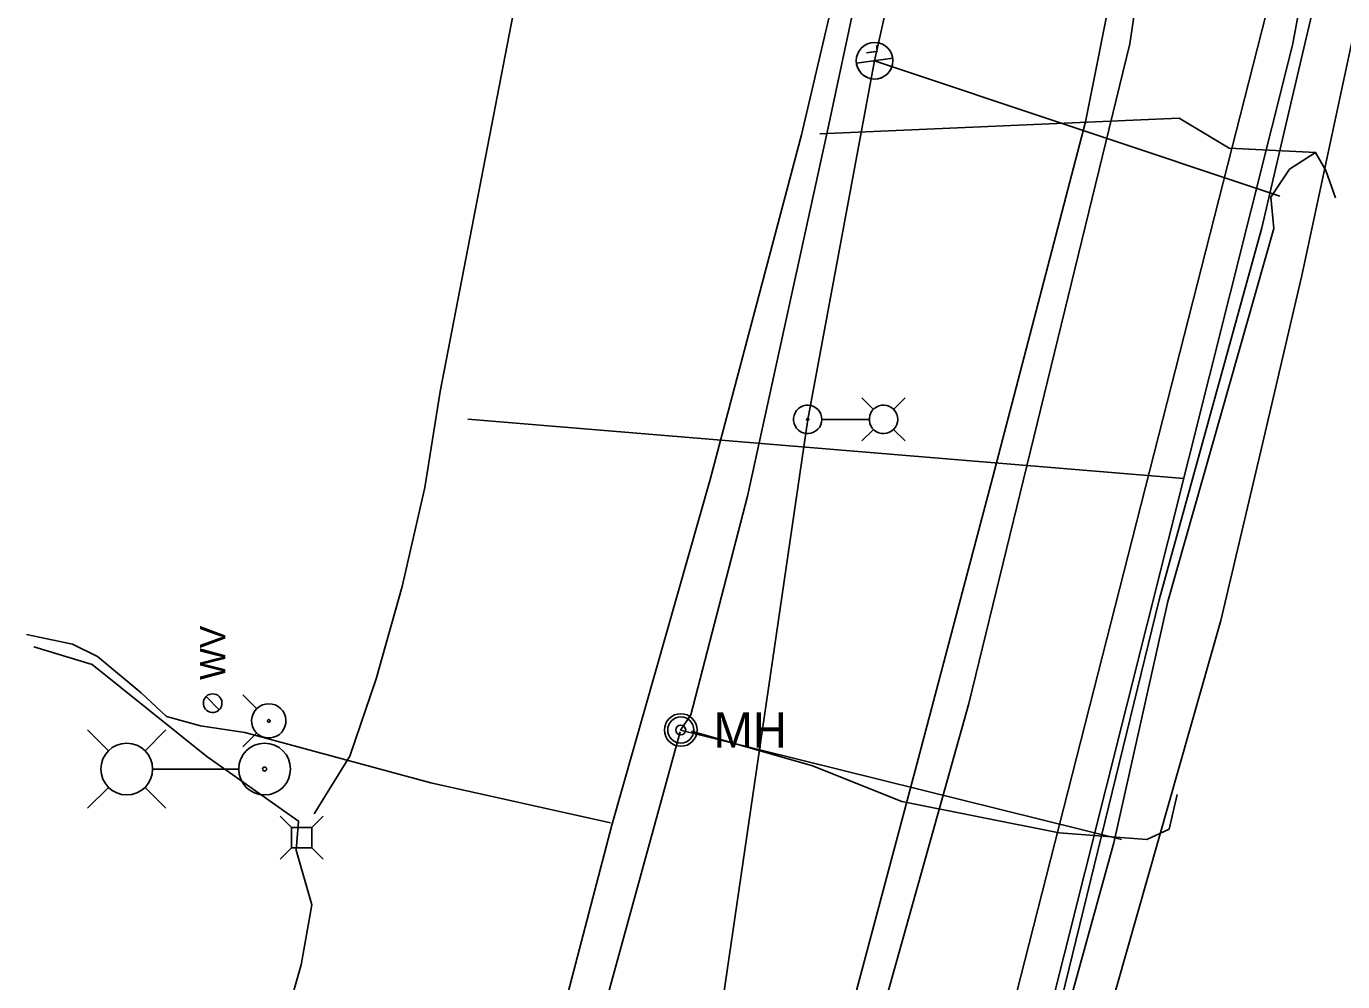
# Model space of a CAD drawing. Extents: x 596028 to 606371, y 330010 to 403088.
# Drawn here: x 604917.4 to 605119, y 336464.1 to 336610.4 of the extents above; entities that cross this region are included whole.
import ezdxf

# ---------------------------------------------------------------- set-up
doc = ezdxf.new("R2010")
doc.units = 0
for name, color, linetype in [('Default', 7, 'Continuous'), ('E_LTG', 7, 'Continuous'), ('E_LTG_CID', 7, 'Continuous'), ('E_UTL_E', 7, 'Continuous'), ('E_UTL_E_UG', 7, 'Continuous'), ('E_UTL_G_UG', 7, 'Continuous'), ('E_UTL_SAN_UG', 7, 'Continuous'), ('E_UTL_TV_UG', 7, 'Continuous'), ('E_UTL_W', 7, 'Continuous'), ('E_UTL_W_UG', 7, 'Continuous'), ('E_UTL_WHydrant', 7, 'Continuous')]:
    doc.layers.add(name, color=color, linetype=linetype)

# ---------------------------------------------------------------- blocks, each defined once
blk = doc.blocks.new('MH')
at = {"layer": 'Default'}
for radius in [15.2, 12.2, 4.57]:
    blk.add_circle((0, 0), radius, dxfattribs=at)
blk.add_text('MH', height=32.92, dxfattribs=at).set_placement((30.5, -16.5))
blk = doc.blocks.new('_U272')
at = {"layer": 'E_LTG'}
blk.add_lwpolyline([(0.001, -0.171), (0.001, 0.172)], dxfattribs=at)
blk.add_circle((0.001, 0), 0.171, dxfattribs=at)
blk.add_arc((0.001, 0), 0.171, 90, 270, dxfattribs=at)
blk.add_text('L', height=0.108, dxfattribs=at).set_placement((0.066, -0.042))

msp = doc.modelspace()

# ---------------------------------------------------------------- linework, layer by layer
at = {"layer": 'E_LTG'}
for points in [[(605039.28, 336550.19), (605039.24, 336550.61), (605039.13, 336551), (605038.94, 336551.37), (605038.68, 336551.7), (605038.37, 336551.97), (605038.01, 336552.17), (605037.62, 336552.31), (605037.21, 336552.37), (605036.8, 336552.35), (605036.4, 336552.25), (605036.02, 336552.08), (605035.68, 336551.84), (605035.4, 336551.54), (605035.17, 336551.19), (605035.02, 336550.81), (605034.94, 336550.4), (605034.94, 336549.99), (605035.02, 336549.58), (605035.17, 336549.2), (605035.4, 336548.85), (605035.68, 336548.55), (605036.02, 336548.31), (605036.4, 336548.14), (605036.8, 336548.04), (605037.21, 336548.02), (605037.62, 336548.08), (605038.01, 336548.22), (605038.37, 336548.42), (605038.68, 336548.69), (605038.94, 336549.02), (605039.13, 336549.39), (605039.24, 336549.78), (605039.28, 336550.19)], [(605047.19, 336551.72), (605045.41, 336553.49)], [(605050.89, 336550.19), (605050.85, 336550.61), (605050.73, 336551), (605050.54, 336551.37), (605050.29, 336551.7), (605049.97, 336551.97), (605049.62, 336552.17), (605049.22, 336552.31), (605048.82, 336552.37), (605048.4, 336552.35), (605048, 336552.25), (605047.62, 336552.08), (605047.29, 336551.84), (605047, 336551.54), (605046.78, 336551.19), (605046.62, 336550.81), (605046.55, 336550.4), (605046.55, 336549.99), (605046.62, 336549.58), (605046.78, 336549.2), (605047, 336548.85), (605047.29, 336548.55), (605047.62, 336548.31), (605048, 336548.14), (605048.4, 336548.04), (605048.82, 336548.02), (605049.22, 336548.08), (605049.62, 336548.22), (605049.97, 336548.42), (605050.29, 336548.69), (605050.54, 336549.02), (605050.73, 336549.39), (605050.85, 336549.78), (605050.89, 336550.19)], [(605050.24, 336551.72), (605052.01, 336553.49)], [(605037.27, 336550.19), (605037.27, 336550.23), (605037.26, 336550.26), (605037.25, 336550.28), (605037.23, 336550.31), (605037.2, 336550.33), (605037.18, 336550.35), (605037.15, 336550.36), (605037.12, 336550.36), (605037.08, 336550.36), (605037.05, 336550.35), (605037.03, 336550.34), (605037, 336550.32), (605036.98, 336550.3), (605036.96, 336550.27), (605036.95, 336550.24), (605036.94, 336550.21), (605036.94, 336550.18), (605036.95, 336550.15), (605036.96, 336550.12), (605036.98, 336550.09), (605037, 336550.07), (605037.03, 336550.05), (605037.05, 336550.04), (605037.08, 336550.03), (605037.12, 336550.03), (605037.15, 336550.03), (605037.18, 336550.04), (605037.2, 336550.06), (605037.23, 336550.08), (605037.25, 336550.1), (605037.26, 336550.13), (605037.27, 336550.16), (605037.27, 336550.19)], [(605046.5, 336550.19), (605039.32, 336550.19)], [(605047.19, 336548.67), (605045.41, 336546.89)], [(605050.24, 336548.67), (605052.01, 336546.89)], [(604930.06, 336499.42), (604926.83, 336502.66)], [(604935.6, 336499.42), (604938.83, 336502.66)], [(604936.85, 336496.66), (604949.9, 336496.66)], [(604930.06, 336493.88), (604926.83, 336490.66)], [(604935.6, 336493.88), (604938.83, 336490.66)]]:
    msp.add_lwpolyline(points, dxfattribs=at)
for centre, radius in [((604932.83, 336496.66), 3.96), ((604953.93, 336496.66), 3.96), ((604953.93, 336496.66), 0.303)]:
    msp.add_circle(centre, radius, dxfattribs=at)
at = {"layer": 'E_LTG_CID'}
for p, q in [((605047.35, 336605.1), (605062.02, 336670.68)), ((605037.11, 336550.19), (605047.35, 336605.1)), ((605047.35, 336605.1), (605109.39, 336584.35)), ((605021.55, 336443.99), (605037.11, 336550.19))]:
    msp.add_line(p, q, dxfattribs=at)
at = {"layer": 'E_UTL_E'}
for points in [[(604958.06, 336487.7), (604956.31, 336489.45)], [(604961.16, 336487.7), (604962.91, 336489.45)], [(604961.16, 336487.7), (604958.06, 336487.7)], [(604958.06, 336487.7), (604958.06, 336484.6)], [(604961.16, 336484.6), (604961.16, 336487.7)], [(604958.06, 336484.6), (604956.31, 336482.85)], [(604958.06, 336484.6), (604961.16, 336484.6)], [(604961.16, 336484.6), (604962.91, 336482.85)]]:
    msp.add_lwpolyline(points, dxfattribs=at)
at = {"layer": 'E_UTL_E_UG'}
msp.add_line((605017.63, 336502.62), (605085.17, 336485.9), dxfattribs=at)
for points in [[(605008.63, 336196.68), (605057.64, 336368.33), (605060.05, 336372.29), (605064.33, 336397.87), (605068.34, 336425.32), (605074.89, 336456.97), (605090.92, 336522.59), (605106.66, 336579.53), (605110.34, 336595.28), (605128.69, 336673.59), (605128.48, 336717.48), (605129.55, 336741.75), (605130.77, 336763.77), (605133.86, 336788.7), (605136.04, 336801.96), (605136.21, 336812.95)], [(605017.63, 336502.62), (605019.2, 336504.96), (605027.87, 336538.45), (605040.18, 336594.62), (605048.88, 336635.32), (605057.57, 336688.76), (605060.14, 336712.18)], [(604978.48, 336539.75), (604980.81, 336554.49), (605004.37, 336676.15), (604998.72, 336689.57)], [(605156.82, 336431.68), (605123.74, 336422.95), (605082.79, 336416.02), (605077.04, 336420.68), (605075.43, 336424.55), (605082.86, 336457.85), (605100.36, 336519.4), (605106.58, 336545.81), (605112.8, 336572.21), (605121.5, 336612.94)], [(605038.95, 336593.94), (605094.01, 336596.29), (605101.67, 336591.74), (605114.91, 336591.07)], [(605048.22, 336327.34), (605057.76, 336360.86), (605061.45, 336372.02), (605066.54, 336397.15), (605069.8, 336425.19), (605075.97, 336456.38), (605083.96, 336485.36), (605092.27, 336522.32), (605108.48, 336579.43), (605108.03, 336584.2), (605110.9, 336588.52), (605114.89, 336591.08)], [(605117.92, 336584.11), (605116.44, 336588.3), (605114.89, 336591.08)], [(604961.55, 336489.78), (604966.97, 336498.61), (604971.01, 336510.46), (604975.01, 336524.61), (604978.48, 336539.75)], [(604944.06, 336408.07), (604949.59, 336431.56), (604952.65, 336440.99), (604955.83, 336453.64), (604959.54, 336466.69), (604961.17, 336475.89), (604958.78, 336484.26), (604959.14, 336488.7), (604945.07, 336498.57), (604927.52, 336512.65), (604918.57, 336515.36)], [(604964.23, 336308.17), (605017.56, 336502.37)], [(605019.29, 336502.46), (605037.84, 336497.17), (605051.54, 336491.67), (605075.63, 336486.92), (605089.05, 336485.89), (605092.45, 336487.46), (605093.7, 336492.77)]]:
    msp.add_lwpolyline(points, dxfattribs=at)
at = {"layer": 'E_UTL_G_UG'}
for points in [[(604947.77, 336280.3), (604969.19, 336351.45), (604980.36, 336393.71), (604994.86, 336441.23), (605007.11, 336488.05), (605022.16, 336540.99), (605036.14, 336593.75), (605045.56, 336633.88), (605050.72, 336657.87), (605053.8, 336682.24), (605055.24, 336717.3)], [(605007.72, 336337.72), (605021.94, 336383.75), (605039.69, 336444.37), (605053.58, 336496.44), (605065.41, 336541.18), (605079.67, 336595.77), (605088.28, 336639.05), (605093.42, 336677.26), (605096.52, 336717.08)], [(604917.45, 336517.24), (604924.54, 336515.76), (604928.37, 336513.87), (604935.02, 336508.34), (604938.91, 336504.71), (604944.14, 336503.3), (604950.91, 336502.28), (604979.4, 336494.54), (605006.92, 336488.45)]]:
    msp.add_lwpolyline(points, dxfattribs=at)
at = {"layer": 'E_UTL_SAN_UG'}
msp.add_line((605049.89, 336386.93), (605122.9, 336673.59), dxfattribs=at)
at = {"layer": 'E_UTL_TV_UG'}
msp.add_line((604985.07, 336550.23), (605094.7, 336541.16), dxfattribs=at)
msp.add_lwpolyline([(605060.52, 336404.97), (605111.34, 336607.47), (605123.74, 336673.87), (605132.43, 336751.8), (605132.43, 336837.89)], dxfattribs=at)
at = {"layer": 'E_UTL_W'}
for points in [[(604945.98, 336508.18), (604945.71, 336508.15), (604945.45, 336508.07), (604945.21, 336507.95), (604945, 336507.78), (604944.82, 336507.58), (604944.69, 336507.34), (604944.6, 336507.09), (604944.56, 336506.82), (604944.57, 336506.55), (604944.64, 336506.28), (604944.75, 336506.04), (604944.9, 336505.82), (604945.1, 336505.63), (604945.33, 336505.48), (604945.58, 336505.38), (604945.85, 336505.33), (604946.12, 336505.33), (604946.38, 336505.38), (604946.64, 336505.48), (604946.86, 336505.63), (604947.06, 336505.82), (604947.22, 336506.04), (604947.33, 336506.28), (604947.39, 336506.55), (604947.41, 336506.82), (604947.37, 336507.09), (604947.28, 336507.34), (604947.14, 336507.58), (604946.97, 336507.78), (604946.75, 336507.95), (604946.51, 336508.07), (604946.25, 336508.15), (604945.98, 336508.18)], [(604946.99, 336505.74), (604944.97, 336507.76)]]:
    msp.add_lwpolyline(points, dxfattribs=at)
at = {"layer": 'E_UTL_W_UG'}
msp.add_line((605086.46, 336607.72), (605104.13, 336727.84), dxfattribs=at)
msp.add_lwpolyline([(604950.66, 336110.15), (605061.8, 336506.7), (605086.46, 336607.72)], dxfattribs=at)
at = {"layer": 'E_UTL_WHydrant'}
for points in [[(604952.74, 336505.87), (604950.6, 336508.01)], [(604954.57, 336506.66), (604954.08, 336506.61), (604953.6, 336506.47), (604953.16, 336506.24), (604952.76, 336505.93), (604952.44, 336505.56), (604952.19, 336505.12), (604952.03, 336504.65), (604951.95, 336504.16), (604951.98, 336503.66), (604952.1, 336503.18), (604952.3, 336502.72), (604952.59, 336502.32), (604952.95, 336501.97), (604953.37, 336501.7), (604953.84, 336501.52), (604954.32, 336501.42), (604954.82, 336501.42), (604955.31, 336501.52), (604955.78, 336501.7), (604956.2, 336501.97), (604956.56, 336502.32), (604956.85, 336502.72), (604957.05, 336503.18), (604957.17, 336503.66), (604957.19, 336504.16), (604957.12, 336504.65), (604956.96, 336505.12), (604956.71, 336505.56), (604956.38, 336505.93), (604955.99, 336506.24), (604955.55, 336506.47), (604955.07, 336506.61), (604954.57, 336506.66)], [(604954.57, 336504.23), (604954.54, 336504.23), (604954.5, 336504.22), (604954.47, 336504.2), (604954.44, 336504.18), (604954.41, 336504.15), (604954.39, 336504.12), (604954.38, 336504.08), (604954.37, 336504.04), (604954.38, 336504.01), (604954.38, 336503.97), (604954.4, 336503.93), (604954.42, 336503.9), (604954.45, 336503.88), (604954.48, 336503.86), (604954.52, 336503.84), (604954.55, 336503.83), (604954.59, 336503.83), (604954.63, 336503.84), (604954.67, 336503.86), (604954.7, 336503.88), (604954.73, 336503.9), (604954.75, 336503.93), (604954.76, 336503.97), (604954.77, 336504.01), (604954.77, 336504.04), (604954.77, 336504.08), (604954.76, 336504.12), (604954.74, 336504.15), (604954.71, 336504.18), (604954.68, 336504.2), (604954.65, 336504.22), (604954.61, 336504.23), (604954.57, 336504.23)], [(604952.74, 336502.2), (604950.6, 336500.06)]]:
    msp.add_lwpolyline(points, dxfattribs=at)

# ---------------------------------------------------------------- block references
at = {"layer": 'E_LTG_CID', "xscale": 16.404166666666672, "yscale": 16.404166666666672, "rotation": 97.82095686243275}
msp.add_blockref('_U272', (605047.35, 336605.09), dxfattribs=at)
at = {"layer": 'E_UTL_E', "xscale": 0.16404166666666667, "yscale": 0.16404166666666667}
msp.add_blockref('MH', (605017.67, 336502.64), dxfattribs=at)

# ---------------------------------------------------------------- texts
at = {"layer": 'E_UTL_W'}
msp.add_text('WV', height=3.85, rotation=90, dxfattribs=at).set_placement((604947.91, 336510.31))

doc.saveas('drawing.dxf')
